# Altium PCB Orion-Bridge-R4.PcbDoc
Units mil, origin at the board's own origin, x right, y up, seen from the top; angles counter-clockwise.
Board outline 1889.76 x 1259.84 mil, 2 copper layers (Top Layer, Bottom Layer), stack 62.992 mil thick; 52 components, 35 nets, 164 pads, 41 vias.
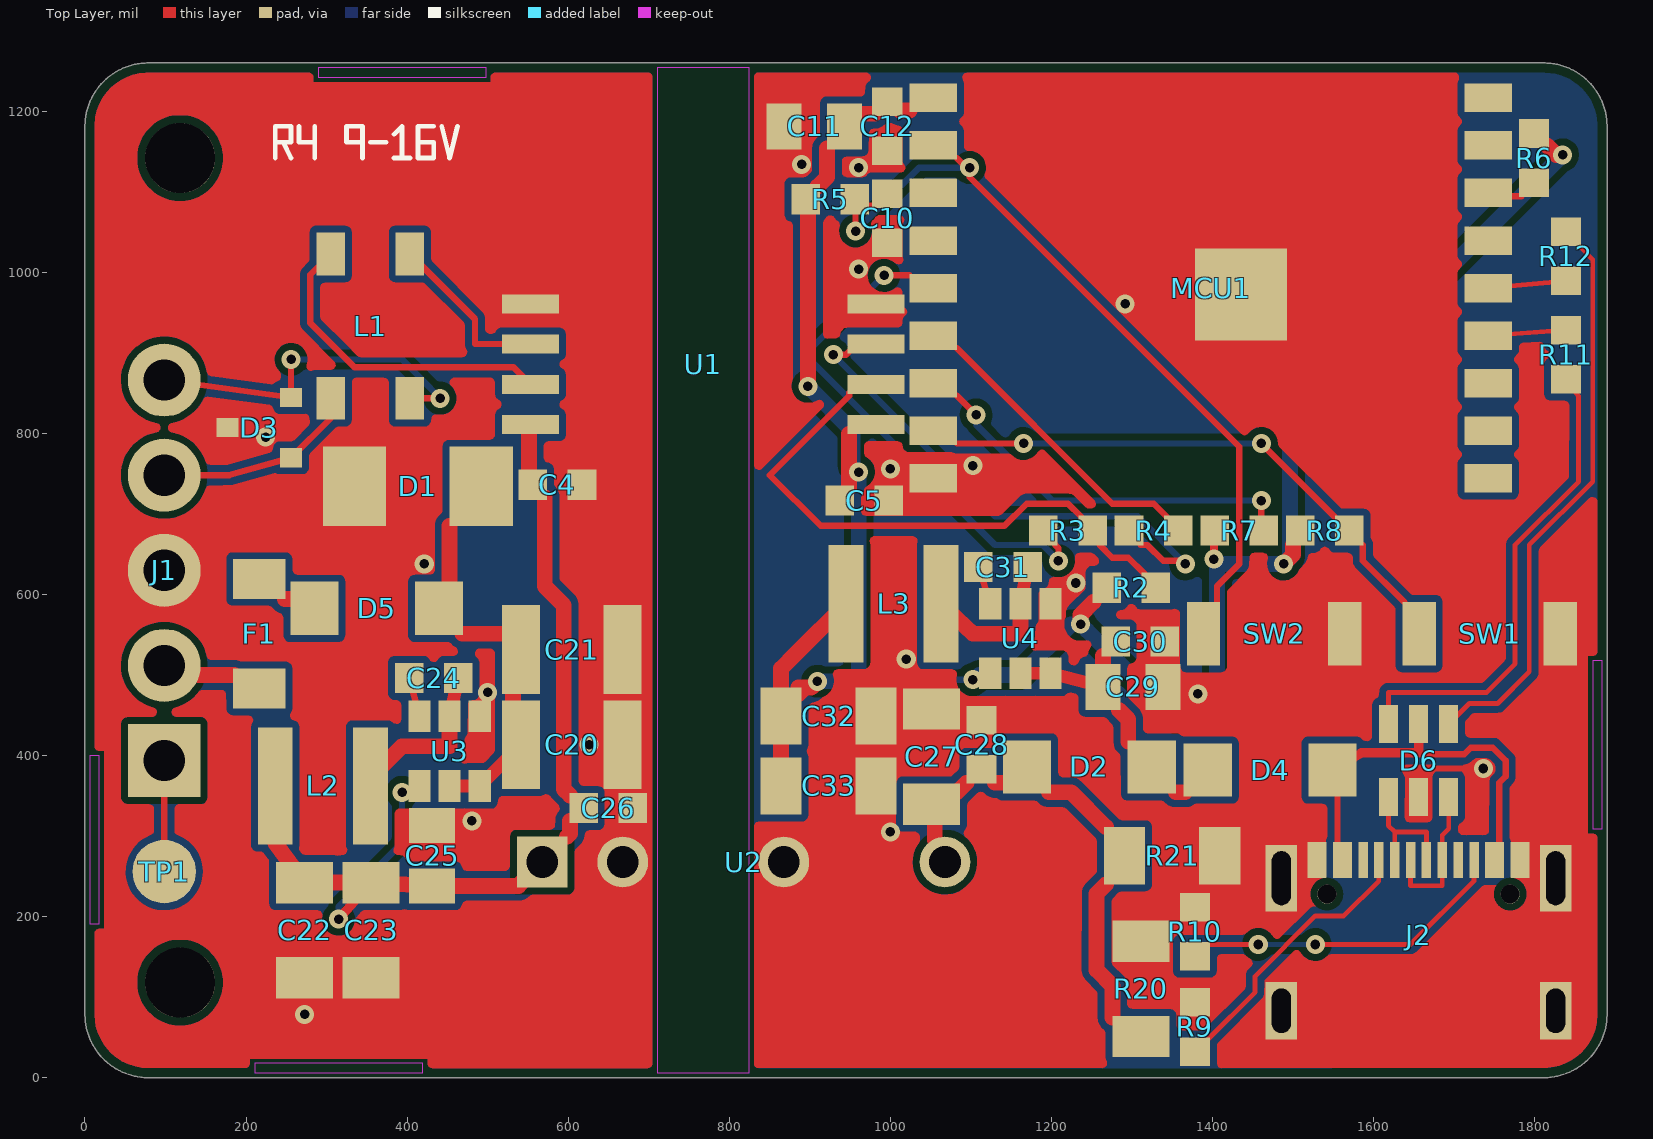
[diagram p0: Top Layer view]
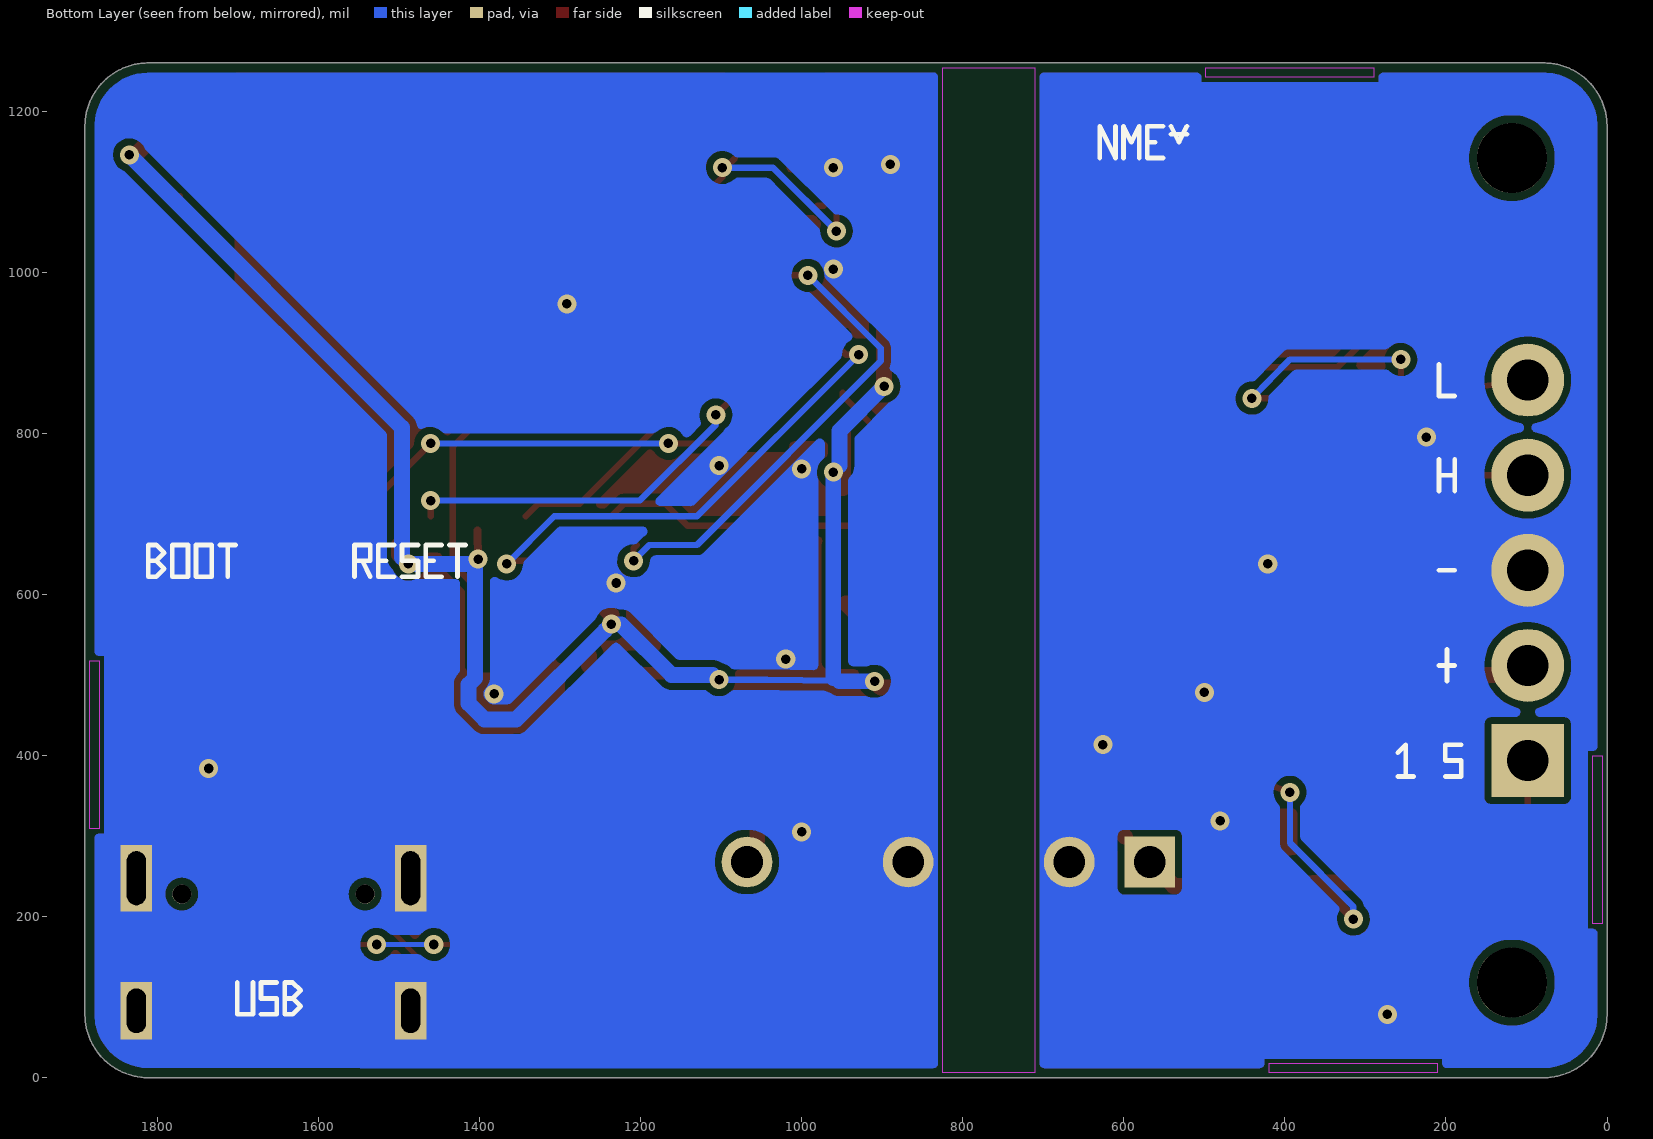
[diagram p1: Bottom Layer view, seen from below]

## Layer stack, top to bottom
Top Solder: solder mask 0.3937, Solder Resist, Dk 3.5
Top Layer: signal copper 1.378
Dielectric1: dielectric 60.2362, FR-4, Dk 4.3
Bottom Layer: signal copper 1.378
Bottom Solder: solder mask 0.3937, Solder Resist, Dk 3.5

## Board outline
1811.02,0 1812.96,0.02 1814.89,0.09 1816.82,0.21 1818.74,0.38 1820.66,0.59 1822.58,0.85 1824.49,1.16 1826.39,1.51 1828.28,1.91 1830.16,2.36 1832.02,2.85 1833.88,3.39 1835.72,3.97 1837.55,4.6 1839.36,5.28 1841.16,5.99 1842.93,6.76 1844.69,7.56 1846.43,8.41 1848.14,9.3 1849.83,10.23 1851.5,11.2 1853.15,12.22 1854.77,13.27 1856.36,14.36 1857.93,15.5 1859.47,16.67 1860.98,17.87 1862.45,19.12 1863.9,20.4 1865.32,21.71 1866.7,23.06 1868.05,24.45 1869.37,25.86 1870.65,27.31 1871.89,28.79 1873.1,30.3 1874.27,31.83 1875.4,33.4 1876.49,34.99 1877.55,36.61 1878.56,38.26 1879.53,39.93 1880.47,41.62 1881.36,43.34 1882.2,45.07 1883.01,46.83 1883.77,48.61 1884.49,50.4 1885.16,52.21 1885.79,54.04 1886.37,55.88 1886.91,57.74 1887.4,59.61 1887.85,61.49 1888.25,63.38 1888.6,65.28 1888.91,67.19 1889.17,69.1 1889.38,71.02 1889.55,72.95 1889.67,74.88 1889.74,76.81 1889.76,78.74 1889.76,1181.1 1889.74,1183.03 1889.67,1184.97 1889.55,1186.89 1889.38,1188.82 1889.17,1190.74 1888.91,1192.66 1888.6,1194.56 1888.25,1196.46 1887.85,1198.35 1887.4,1200.23 1886.91,1202.1 1886.37,1203.96 1885.79,1205.8 1885.16,1207.63 1884.49,1209.44 1883.77,1211.23 1883.01,1213.01 1882.2,1214.77 1881.36,1216.5 1880.47,1218.22 1879.53,1219.91 1878.56,1221.58 1877.55,1223.23 1876.49,1224.85 1875.4,1226.44 1874.27,1228.01 1873.1,1229.55 1871.89,1231.05 1870.65,1232.53 1869.37,1233.98 1868.05,1235.4 1866.7,1236.78 1865.32,1238.13 1863.9,1239.44 1862.45,1240.73 1860.98,1241.97 1859.47,1243.18 1857.93,1244.35 1856.36,1245.48 1854.77,1246.57 1853.15,1247.63 1851.5,1248.64 1849.83,1249.61 1848.14,1250.55 1846.43,1251.43 1844.69,1252.28 1842.93,1253.09 1841.16,1253.85 1839.36,1254.57 1837.55,1255.24 1835.72,1255.87 1833.88,1256.45 1832.02,1256.99 1830.16,1257.48 1828.28,1257.93 1826.39,1258.33 1824.49,1258.68 1822.58,1258.99 1820.66,1259.25 1818.74,1259.46 1816.82,1259.63 1814.89,1259.75 1812.96,1259.82 1811.02,1259.84 78.74,1259.84 76.81,1259.82 74.88,1259.75 72.95,1259.63 71.02,1259.46 69.1,1259.25 67.19,1258.99 65.28,1258.68 63.38,1258.33 61.49,1257.93 59.61,1257.48 57.74,1256.99 55.88,1256.45 54.04,1255.87 52.21,1255.24 50.4,1254.57 48.61,1253.85 46.83,1253.09 45.07,1252.28 43.34,1251.43 41.62,1250.55 39.93,1249.61 38.26,1248.64 36.61,1247.63 34.99,1246.57 33.4,1245.48 31.83,1244.35 30.3,1243.18 28.79,1241.97 27.31,1240.73 25.86,1239.44 24.45,1238.13 23.06,1236.78 21.71,1235.4 20.4,1233.98 19.12,1232.53 17.87,1231.05 16.67,1229.55 15.5,1228.01 14.36,1226.44 13.27,1224.85 12.22,1223.23 11.2,1221.58 10.23,1219.91 9.3,1218.22 8.41,1216.5 7.56,1214.77 6.76,1213.01 5.99,1211.23 5.28,1209.44 4.6,1207.63 3.97,1205.8 3.39,1203.96 2.85,1202.1 2.36,1200.23 1.91,1198.35 1.51,1196.46 1.16,1194.56 0.85,1192.66 0.59,1190.74 0.38,1188.82 0.21,1186.89 0.09,1184.97 0.02,1183.03 0,1181.1 0,78.74 0.02,76.81 0.09,74.88 0.21,72.95 0.38,71.02 0.59,69.1 0.85,67.19 1.16,65.28 1.51,63.38 1.91,61.49 2.36,59.61 2.85,57.74 3.39,55.88 3.97,54.04 4.6,52.21 5.28,50.4 5.99,48.61 6.76,46.83 7.56,45.07 8.41,43.34 9.3,41.62 10.23,39.93 11.2,38.26 12.22,36.61 13.27,34.99 14.36,33.4 15.5,31.83 16.67,30.3 17.87,28.79 19.12,27.31 20.4,25.86 21.71,24.45 23.06,23.06 24.45,21.71 25.86,20.4 27.31,19.12 28.79,17.87 30.3,16.67 31.83,15.5 33.4,14.36 34.99,13.27 36.61,12.22 38.26,11.2 39.93,10.23 41.62,9.3 43.34,8.41 45.07,7.56 46.83,6.76 48.61,5.99 50.4,5.28 52.21,4.6 54.04,3.97 55.88,3.39 57.74,2.85 59.61,2.36 61.49,1.91 63.38,1.51 65.28,1.16 67.19,0.85 69.1,0.59 71.02,0.38 72.95,0.21 74.88,0.09 76.81,0.02 78.74,0

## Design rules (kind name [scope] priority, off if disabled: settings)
BoardOutlineClearance BoardEdge_0_30mm [All] p1: gap=11.81 ignorepadtopadclearanceinfootprint=FALSE
Clearance Isolation_BUS_LOGIC [InNet('5V_BUS') Or InNet('BST_BUS') Or InNet('BUS_PROT') Or InNet('CANH') Or InNet('CANH_EXT') Or InNet('CANL') Or InNet('CANL_EXT') Or InNet('FUSED_IN') Or InNet('GND_BUS') Or InNet('NET_S') Or InNet('SHIELD') Or InNet('SW_BUS') vs InNet('3V3_LOGIC') Or InNet('5V_ISO') Or InNet('5V_SYS') Or InNet('BST_LOGIC') Or InNet('ESP_BOOT') Or InNet('ESP_EN') Or InNet('ESP_GPIO2') Or InNet('ESP_GPIO8') Or InNet('GND_LOGIC') Or InNet('GPIO6') Or InNet('GPIO7') Or InNet('RXD') Or InNet('SW_LOGIC') Or InNet('TXD') Or InNet('USB_CC1') Or InNet('USB_CC2') Or InNet('USB_DM') Or InNet('USB_DM_IN') Or InNet('USB_DM_MCU') Or InNet('USB_DP') Or InNet('USB_DP_IN') Or InNet('USB_DP_MCU') Or InNet('USB_VBUS')] p1: gap=125.98 ignorepadtopadclearanceinfootprint=FALSE
Clearance Mounting_NPTH [IsPad And (HoleSize > 0) And (PadIsPlated = 'False') And (Not InComponent('J2'))] p2: gap=9.84 ignorepadtopadclearanceinfootprint=FALSE
Clearance USB_Alignment_NPTH [IsPad And (HoleSize > 0) And (PadIsPlated = 'False') And InComponent('J2')] p3: gap=7.87 ignorepadtopadclearanceinfootprint=FALSE
Clearance [All] p4: gap=5.91 ignorepadtopadclearanceinfootprint=FALSE
ComponentClearance [All] p1: gap=9.84 collisioncheckmode=3 verticalgap=9.84 showdistances=FALSE
HoleSize [All] p1: absolutevalues=TRUE maxlimit=248.03 minlimit=11.81 maxpercent=80.000 minpercent=20.000
HoleToHoleClearance [All] p1: gap=9.84 allowstackedmicrovias=FALSE
MinimumAnnularRing PTH_AnnularRing [IsPad And (PadIsPlated = 'True')] p1: minimumring=7.09
MinimumAnnularRing Via_AnnularRing [IsVia] p2: minimumring=5.91
MinimumSolderMaskSliver [All] p1: minsoldermaskwidth=3.94
PasteMaskExpansion Paste_1to1 [All] p1: expansion=0
PolygonConnect [All] p1: connectstyle=Relief reliefconductorwidth=10 reliefentries=4 polygonreliefangle="90 Angle" airgapwidth=10
RoutingVias [All] p1: holewidth=11.81 width=23.62 viastyle="Through Hole" minholewidth=11.81 minwidth=23.62 maxholewidth=11.81 maxwidth=23.62
SilkToSilkClearance SilkToSilk [All] p1: silktosilkclearance=3.94
SilkToSolderMaskClearance SilkToMask_0_15mm [IsPad] p1: minsilkscreentomaskgap=5.91 clearancetoexposedcopper=FALSE
SolderMaskExpansion TentedVias [IsVia] p1: expansion=-11.81 istentingtop=TRUE
SolderMaskExpansion PadSolderMask [All] p2: expansion=1.97 istentingtop=FALSE
SupplyNets "Schematic Supply Nets_1" [InNet('GND_BUS')] p1: voltage=0.000
SupplyNets "Schematic Supply Nets" [InNet('GND_LOGIC')] p2: voltage=0.000
Width USB_FullSpeed [InNet('USB_CC1') Or InNet('USB_CC2') Or InNet('USB_DM') Or InNet('USB_DM_IN') Or InNet('USB_DM_MCU') Or InNet('USB_DP') Or InNet('USB_DP_IN') Or InNet('USB_DP_MCU')] p1: maxlimit=19.68 minlimit=5.91 preferedwidth=5.91
Width [All] p2: maxlimit=78.74 minlimit=7.87 preferedwidth=11.81
23 further rules are at their usual default settings.

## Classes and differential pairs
component class Orion-Bridge-R4-Power: C20 C21 C22 C23 C24 C25 C26 C27 C28 C29 C30 C31 C32 C33 D1 D2 D4 D5 F1 J1 L2 L3 R20 R21 TP1 U2 U3 U4
component class Orion-Bridge-R4-Logic: C4 C5 C10 C11 C12 D3 D6 J2 L1 MCU1 R2 R3 R4 R5 R6 R7 R8 R9 R10 R11 R12 SW1 SW2 U1

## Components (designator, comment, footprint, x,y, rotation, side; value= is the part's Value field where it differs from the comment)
C4 "100nF 50V X7R" C0603#1 586.61,736.22 r0 top
C5 "100nF 50V X7R" C0603#2 967.52,716.54 r0 top
C10 "1uF 50V X5R" C0603#2 996.06,1066.93 r270 top
C11 "10uF 25V X5R" C0805 905.51,1181.1 r180 top
C12 "100nF 50V X7R" C0603#2 996.06,1181.1 r270 top
C20 "10uF 50V X7R" C1210#1 604.33,413.39 r0 top
C21 "10uF 50V X7R" C1210#2 604.33,531.5 r0 top
C22 "22uF 25V X5R" C1206 272.64,183.07 r270 top
C23 "22uF 25V X5R" C1206 355.31,183.07 r270 top
C24 "100nF 50V X7R" C0603#2 433.07,496.06 r0 top
C25 "10uF 25V X5R" C0805 431.1,275.59 r90 top
C26 "100nF 50V X7R" C0603#3 649.61,334.65 r0 top
C27 "22uF 25V X5R" C1206 1051.18,398.62 r90 top
C28 "100nF 50V X7R" C0603#4 1113.19,413.39 r90 top
C29 "10uF 25V X5R" C0805 1301.18,485.24 r0 top
C30 "100nF 50V X7R" C0603#2 1310.04,541.34 r0 top
C31 "100nF 50V X7R" C0603#5 1139.76,633.86 r0 top
C32 "22uF 25V X5R" C1206 923.23,448.82 r0 top
C33 "22uF 25V X5R" C1206 923.23,362.2 r0 top
D1 "SMBJ18A 600W" SMB 413.39,734.25 r180 top
D2 "SS14 1A 40V" SMA#1 1247.05,385.83 r180 top
D3 "PESD2CAN24T-Q" SOT23_NEXPERIA_REFLOW 216.54,807.09 r90 top
D4 "SS14 1A 40V" SMA#1 1471.46,381.89 r0 top
D5 "SS26 2A 60V" SMA#2 362.2,582.68 r180 top
D6 "USBLC6-2SC6" SOT23_6_ST_USBLC6 1655.71,393.7 r0 top
F1 "T0.8A 63VDC" BOURNS_SF1206S 216.54,551.18 r90 top
J1 "NMEA Micro-C pigtail" PIGTAIL_5_P3_D1P3 98.43,629.92 r180 top
J2 "TYPE-C-31-M-12" USB_C_HRO_TYPE_C_31_M_12_2020 1655.71,125.59 r0 top
L1 "ACT45B-510-2P-TL003" ACT45B 354.33,933.07 r90 top
L2 "4.7uH" SUNLORD_SWPA4030 295.28,362.2 r180 top
L3 "4.7uH" SUNLORD_SWPA4030 1003.94,588.58 r180 top
MCU1 "ESP32-C3-WROOM-02-N4" ESP32_C3_WROOM_02 1397.64,1102.36 r0 top
R2 "10k 1% 0.1W" R0603 1299.21,608.27 r0 top
R3 "33R" R0603 1220.47,679.13 r0 top
R4 "33R" R0603 1326.77,679.13 r0 top
R5 "10k 1% 0.1W" R0603 925.2,1090.55 r0 top
R6 "10k 1% 0.1W" R0603 1799.21,1141.73 r270 top
R7 "10k 1% 0.1W" R0603 1433.07,679.13 r0 top
R8 "10k 1% 0.1W" R0603 1539.37,679.13 r0 top
R9 "5.1k 1% 0.1W" R0603 1377.95,62.99 r90 top
R10 "5.1k 1% 0.1W" R0603 1377.95,181.1 r90 top
R11 "22R 1% 0.1W" R0603 1838.58,897.64 r90 top
R12 "22R 1% 0.1W" R0603 1838.58,1019.68 r270 top
R20 "150R 1% 0.5W" R1206 1311.02,110.24 r90 top
R21 "150R 1% 0.5W" R1206 1349.8,275.59 r0 top
SW1 "TS-1088-AR02016" SW_XUNPU_TS1088_AR 1744.09,551.18 r0 top
SW2 "TS-1088-AR02016" SW_XUNPU_TS1088_AR 1476.38,551.18 r0 top
TP1 "Shield / chassis pad" TESTPOINT_2MM 98.43,255.91 r0 top
U1 "ISO1042DWV" SOIC8_DWV 767.72,885.83 r180 top
U2 "B0505S-3WR2" EVISUN_B0505S_3WR2 867.52,165.35 r0 top
U3 "AP63205WU-7" TSOT26_DIODES 452.76,405.51 r0 top
U4 "AP63203WU-7" TSOT26_DIODES 1161.42,545.28 r0 top

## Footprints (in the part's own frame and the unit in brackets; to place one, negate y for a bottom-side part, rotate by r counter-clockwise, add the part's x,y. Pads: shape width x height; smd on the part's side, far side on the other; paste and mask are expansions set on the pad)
ACT45B [mm] "TDK ACT45B recommended lands; windings 1-4 and 2-3"
  rect 1.35x0.9 smd: 1(-2.275,1.25) 2(-2.275,-1.25) 3(2.275,-1.25) 4(2.275,1.25)
  body extent -2.53,-1.6 2.52,1.6, height 2.8
BOURNS_SF1206S [mm] "Bourns SF-1206S recommended land pattern: total X span 4.7, inner gap 2.2, pad Y 1.65; maximum body envelope. No polarity."
  rect 1.25x1.65 smd: 1(-1.725,0)
  rect 1.25x1.65 smd mask+0.02: 2(1.725,0)
  body extent -1.6,-0.83 1.6,0.83, height 0.71
C0603#1 [mm] "IPC-style 0603 solder lands; selected MPN dimensions reviewed separately."
  rect 0.9x0.95 smd mask+0.015: 1(-0.775,0)
  rect 0.9x0.95 smd: 2(0.775,0)
  body extent -0.8,-0.41 0.8,0.41, height 0.81
C0603#2 [mm] "IPC-style 0603 solder lands; selected MPN dimensions reviewed separately."
  rect 0.9x0.95 smd: 1(-0.775,0) 2(0.775,0)
  body extent -0.8,-0.41 0.8,0.41, height 0.81
C0603#3 [mm] "IPC-style 0603 solder lands; selected MPN dimensions reviewed separately."
  rect 0.9x0.95 smd mask+0.01: 1(-0.775,0) 2(0.775,0)
  body extent -0.8,-0.41 0.8,0.41, height 0.81
C0603#4 [mm] "IPC-style 0603 solder lands; selected MPN dimensions reviewed separately."
  rect 0.9x0.95 smd: 1(-0.775,0)
  rect 0.9x0.95 smd mask+0.025: 2(0.775,0)
  body extent -0.8,-0.41 0.8,0.41, height 0.81
C0603#5 [mm] "IPC-style 0603 solder lands; selected MPN dimensions reviewed separately."
  rect 0.9x0.95 smd mask+0.015: 1(-0.775,0) 2(0.775,0)
  body extent -0.8,-0.41 0.8,0.41, height 0.81
C0805 [mm] "IPC-style 0805 solder lands; selected MPN dimensions reviewed separately."
  rect 1.1x1.45 smd: 1(-0.95,0) 2(0.95,0)
  body extent -1,-0.63 1,0.63, height 0.81
C1206 [mm] "IPC-style 1206 solder lands; selected MPN dimensions reviewed separately."
  rect 1.3x1.8 smd: 1(-1.5,0) 2(1.5,0)
  body extent -1.6,-0.81 1.6,0.81, height 1.52
C1210#1 [mm] "Samsung CL32B106KBJNNNE body3.2x2.5mm, nominal1210 land pattern selected."
  rect 1.2x2.8 smd: 1(-1.6,0)
  rect 1.2x2.8 smd mask+0.01: 2(1.6,0)
  body extent -1.6,-1.26 1.6,1.26, height 2.72
C1210#2 [mm] "Samsung CL32B106KBJNNNE body3.2x2.5mm, nominal1210 land pattern selected."
  rect 1.2x2.8 smd: 1(-1.6,0) 2(1.6,0)
  body extent -1.6,-1.26 1.6,1.26, height 2.72
ESP32_C3_WROOM_02 [mm] "Espressif WROOM-02 v1.7 Fig11-1. EP19 ground copper with NO paste; optional EP left unsoldered per manufacturer."
  rect 1.5x0.9 smd: 1(-8.75,2.9) 2(-8.75,1.4) 3(-8.75,-0.1) 4(-8.75,-1.6) 9(-8.75,-9.1) 10(8.75,-9.1) 11(8.75,-7.6) 12(8.75,-6.1) 13(8.75,-4.6) 14(8.75,-3.1) 15(8.75,-1.6) 16(8.75,-0.1) 17(8.75,1.4) 18(8.75,2.9)
  rect 1.5x0.9 smd mask+0.02: 5(-8.75,-3.1) 6(-8.75,-4.6) 7(-8.75,-6.1) 8(-8.75,-7.6)
  rect 2.9x2.9 smd paste-10: 19(0.96,-3.3)
  body extent -9,-10 9,10, height 3.35
EVISUN_B0505S_3WR2 [mm] "EVISUN p4: nominal19.65x7x10.16mm, unspecified body tolerance+/-0.25mm, lead1 x=2.21 from body left, pitch1-2=2.54/2-4=5.08/4-6=5.08mm. Pin row .90mm from long body edge. Bottom view mirrored vertically to PCB TOP: row Y=+2.60mm. Finished holes1.00mm, annulus.30mm. Primary/secondary pad copper gap3.48mm."
  rect 1.6x1.6 hole 1 paste-2539.97: 1(-7.615,2.6)
  round 1.6 hole 1 paste-2539.97: 2(-5.075,2.6) 4(0.005,2.6) 6(5.085,2.6)
  body extent -9.82,-3.5 9.82,3.5, height 10.33
PIGTAIL_5_P3_D1P3 [mm] "Designed carrier wire-solder interface, 3.0 pitch, 1.3 finished-hole target, 0.5 radial annulus. Pin numbering is logical NMEA: 1 shield, 2 NET-S, 3 NET-C, 4 CAN-H, 5 CAN-L. Cable and strain relief still require a physical selection."
  rect 2.3x2.3 hole 1.3 paste-2539.97: 1(0,6)
  round 2.3 hole 1.3 paste-2539.97: 2(0,3) 3(0,0) 4(0,-3) 5(0,-6)
  body extent -1.15,-7.15 1.15,7.15, height 0.06
R0603 [mm] "IPC-style 0603 solder lands; selected MPN dimensions reviewed separately."
  rect 0.9x0.95 smd: 1(-0.775,0) 2(0.775,0)
  body extent -0.8,-0.41 0.8,0.41, height 0.81
R1206 [mm] "IPC-style 1206 solder lands; selected MPN dimensions reviewed separately."
  rect 1.3x1.8 smd: 1(-1.5,0) 2(1.5,0)
  body extent -1.6,-0.81 1.6,0.81, height 1.52
SMA#1 [mm] "MDD SS12-SS1200 Rev2025A3 p3 / SS22-SS2200 Rev2024A4 p3 suggested SMA pattern: pad1.52x1.68, centrepitch3.93, innergap2.41, totalX5.45mm. Maxbody4.5x2.8x2.45; pin1Kleft,2Aright. Visually checked selected C2480/C14238 PDFs."
  rect 1.52x1.68 smd: 1(-1.965,0) 2(1.965,0)
  body extent -2.54,-1.4 2.54,1.4, height 2.46
SMA#2 [mm] "MDD SS12-SS1200 Rev2025A3 p3 / SS22-SS2200 Rev2024A4 p3 suggested SMA pattern: pad1.52x1.68, centrepitch3.93, innergap2.41, totalX5.45mm. Maxbody4.5x2.8x2.45; pin1Kleft,2Aright. Visually checked selected C2480/C14238 PDFs."
  rect 1.52x1.68 smd: 1(-1.965,0)
  rect 1.52x1.68 smd mask+0.02: 2(1.965,0)
  body extent -2.54,-1.4 2.54,1.4, height 2.46
SMB [mm] "BORN SMBJ Series Rev2022-Jan-1-A p7 manufacturer pattern: pad2.0x2.5mm, innergap2.0mm, centres+/-2.0mm; maxbody4.7x3.9x2.5; pin1Kleft,2Aright. Visually checked selected C152104 PDF."
  rect 2x2.5 smd: 1(-2,0) 2(2,0)
  body extent -2.58,-1.95 2.57,1.95, height 2.51
SOIC8_DWV [mm] "TI DWV0008A manufacturer land pattern; pin 1 upper left"
  rect 1.8x0.6 smd mask+0.02: 1(-5.45,1.905) 2(-5.45,0.635) 3(-5.45,-0.635) 4(-5.45,-1.905)
  rect 1.8x0.6 smd: 5(5.45,-1.905) 6(5.45,-0.635) 7(5.45,0.635) 8(5.45,1.905)
  body extent -5.7,-2.93 5.7,2.93, height 2.82
SOT23_6_ST_USBLC6 [mm] "ST USBLC6-2 datasheet Fig22 p12; visually checked manufacturer recommended land pattern."
  rect 0.6x1.2 smd: 1(-0.95,-1.15) 2(0,-1.15) 3(0.95,-1.15) 4(0.95,1.15) 5(0,1.15) 6(-0.95,1.15)
  body extent -1.53,-1.4 1.52,1.4, height 1.47
SOT23_NEXPERIA_REFLOW [mm] "Nexperia SOT23 reflow footprint Fig10: 0.6 x 0.7 copper lands, 1.9 pin pitch and 2.0 row centres. Drawing is rotated 180 degrees to match existing top-view pin1 lower left, pin2 lower right, pin3 upper centre. Paste suggested0.5 x0.6, mask opening1.0 x1.0; set fabrication-specific expansions accordingly."
  rect 0.6x0.7 smd: 1(-0.95,-1) 2(0.95,-1) 3(0,1)
  body extent -1.5,-1.25 1.5,1.25, height 1.11
SUNLORD_SWPA4030 [mm] "Sunlord SWPA datasheet2025-05-08 p2 recommended SWPA4030S pattern: gap1.9, padwidth1.1, padheight3.7."
  rect 1.1x3.7 smd: 1(-1.5,0) 2(1.5,0)
  body extent -2,-2 2,2, height 3.02
SW_XUNPU_TS1088_AR [mm] "XUNPU TS-1088-ARXXXXXX manufacturer drawing: outer width5.50, inner gap3.40, padheight2.00; two terminals, no locating posts."
  rect 1.05x2 smd: 1(-2.225,0) 2(2.225,0)
  body extent -2.68,-1.5 2.67,1.5, height 2
TESTPOINT_2MM [mm] "2 mm exposed top-copper test pad; no paste"
  round 2 smd paste-10: 1(0,0)
  body extent -1,-1 1,1, height 0.06
TSOT26_DIODES [mm] "Diodes DS41326 Rev3-2 p17 suggested TSOT26 copper: X=.70,Y=1.00,Y1=3.20 total span,C=.95. Top view: pin1 lower-left; pin4 upper-right."
  rect 0.7x1 smd: 1(-0.95,-1.1) 2(0,-1.1) 3(0.95,-1.1) 4(0.95,1.1) 5(0,1.1) 6(-0.95,1.1)
  body extent -1.5,-1.35 1.5,1.35, height 1.01
USB_C_HRO_TYPE_C_31_M_12_2020 [mm] "HRO drawing dated2020-12-08 downloaded via JLC C165948. NOT older2018 KiCad footprint: updated front slots1.4, padwidth centres3.20/2.40 and padheight1.14. Body envelope3D is nominal. Shield copper enlarged by0.05mm peredge from manufacturer recommendation to provide0.20mm annular ring; drills unchanged."
  rect 0.6x1.14 smd: A1_B12(-3.2,3.67) A4_B9(-2.4,3.67) B1_A12(3.2,3.67) B4_A9(2.4,3.67)
  rect 0.3x1.14 smd: A5(-1.25,3.67) A6(-0.25,3.67) A7(0.25,3.67) A8(1.25,3.67) B5(1.75,3.67) B6(0.75,3.67) B7(-0.75,3.67) B8(-1.75,3.67)
  rect 1x2.1 hole 0.6 slot 1.7 at 90 deg paste-2539.97: S1(-4.325,3.1) S2(4.325,3.1)
  rect 1x1.8 hole 0.6 slot 1.4 at 90 deg paste-2539.97: S3(-4.325,-1.08) S4(4.325,-1.08)
  round 0.6 hole 0.6 unplated paste-2539.97 mask+0.05: ""(-2.89,2.6) ""(2.89,2.6)
  body extent -4.47,-3.68 4.47,4.14, height 3.26

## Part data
C4: library part R4_C4_100nF, "100nF 16V X7R - generic specification; manufacturer/MPN not selected", Manufacturer=YAGEO, Manufacturer Part Number=CC0603KRX7R9BB104, Supplier Part Number 1=C14663
C5: library part R4_C5_100nF, "100nF 16V X7R - generic specification; manufacturer/MPN not selected", Manufacturer=YAGEO, Manufacturer Part Number=CC0603KRX7R9BB104, Supplier Part Number 1=C14663
C10: library part R4_C10_1uF, Manufacturer="Samsung Electro-Mechanics", Manufacturer Part Number=CL10A105KB8NNNC, Supplier Part Number 1=C15849
C11: library part R4_C11_10uF, Manufacturer="Samsung Electro-Mechanics", Manufacturer Part Number=CL21A106KAYNNNE, Supplier Part Number 1=C15850
C12: library part R4_C12_100nF, Manufacturer=YAGEO, Manufacturer Part Number=CC0603KRX7R9BB104, Supplier Part Number 1=C14663
C20: library part R4_C20_10uF, Manufacturer="Samsung Electro-Mechanics", Manufacturer Part Number=CL32B106KBJNNNE, Supplier Part Number 1=C138687
C21: library part R4_C21_10uF, Manufacturer="Samsung Electro-Mechanics", Manufacturer Part Number=CL32B106KBJNNNE, Supplier Part Number 1=C138687
C22: library part R4_C22_22uF, Manufacturer="Samsung Electro-Mechanics", Manufacturer Part Number=CL31A226KAHNNNE, Supplier Part Number 1=C12891
C23: library part R4_C23_22uF, Manufacturer="Samsung Electro-Mechanics", Manufacturer Part Number=CL31A226KAHNNNE, Supplier Part Number 1=C12891
C24: library part R4_C24_100nF, Manufacturer=YAGEO, Manufacturer Part Number=CC0603KRX7R9BB104, Supplier Part Number 1=C14663
C25: library part R4_C25_10uF, Manufacturer="Samsung Electro-Mechanics", Manufacturer Part Number=CL21A106KAYNNNE, Supplier Part Number 1=C15850
C26: library part R4_C26_100nF, Manufacturer=YAGEO, Manufacturer Part Number=CC0603KRX7R9BB104, Supplier Part Number 1=C14663
C27: library part R4_C27_22uF, Manufacturer="Samsung Electro-Mechanics", Manufacturer Part Number=CL31A226KAHNNNE, Supplier Part Number 1=C12891
C28: library part R4_C28_100nF, Manufacturer=YAGEO, Manufacturer Part Number=CC0603KRX7R9BB104, Supplier Part Number 1=C14663
C29: library part R4_C29_10uF, Manufacturer="Samsung Electro-Mechanics", Manufacturer Part Number=CL21A106KAYNNNE, Supplier Part Number 1=C15850
C30: library part R4_C30_100nF, Manufacturer=YAGEO, Manufacturer Part Number=CC0603KRX7R9BB104, Supplier Part Number 1=C14663
C31: library part R4_C31_100nF, Manufacturer=YAGEO, Manufacturer Part Number=CC0603KRX7R9BB104, Supplier Part Number 1=C14663
C32: library part R4_C32_22uF, Manufacturer="Samsung Electro-Mechanics", Manufacturer Part Number=CL31A226KAHNNNE, Supplier Part Number 1=C12891
C33: library part R4_C33_22uF, Manufacturer="Samsung Electro-Mechanics", Manufacturer Part Number=CL31A226KAHNNNE, Supplier Part Number 1=C12891
D1: library part R4_D1_SMBJ18A, Manufacturer=BORN, Manufacturer Part Number=SMBJ18A, Supplier Part Number 1=C152104
D2: library part R4_D2_SS14, Manufacturer="MDD(Microdiode Semiconductor)", Manufacturer Part Number=SS14, Supplier Part Number 1=C2480
D3: library part R4_D3_PESD2CAN24T_Q, Manufacturer=Nexperia, Manufacturer Part Number=PESD2CAN24T-QR, Supplier Part Number 1=C28933048
D4: library part R4_D4_SS14, Manufacturer="MDD(Microdiode Semiconductor)", Manufacturer Part Number=SS14, Supplier Part Number 1=C2480
D5: library part R4_D5_SS26, Manufacturer="MDD(Microdiode Semiconductor)", Manufacturer Part Number=SS26, Supplier Part Number 1=C14238
D6: library part R4_D6_USBLC6_2SC6, Manufacturer=STMicroelectronics, Supplier Part Number 1=C7519
F1: library part R4_F1_T0.8A, "0.8 A slow-blow SMD ceramic fuse, 63 VDC, 50 A interrupt rating", Manufacturer=BOURNS, Manufacturer Part Number=SF-1206S080-2, Supplier Part Number 1=C3032873
J1: library part R4_J1_NMEA, "Five direct wire-solder pads for a separately selected Micro-C cable; this is a PCB interface, not an invented connector MPN or face view"
J2: library part R4_J2_TYPE_C_31_M_12, Manufacturer="Korean Hroparts Elec", Supplier Part Number 1=C165948
L1: library part R4_L1_ACT45B_510_2P_TL003, Manufacturer=TDK, Supplier Part Number 1=C76584
L2: library part R4_L2_4.7uH, Manufacturer=Sunlord, Manufacturer Part Number=SWPA4030S4R7MT, Supplier Part Number 1=C57269
L3: library part R4_L3_4.7uH, Manufacturer=Sunlord, Manufacturer Part Number=SWPA4030S4R7MT, Supplier Part Number 1=C57269
MCU1: library part R4_MCU1_ESP32_C3_WROOM_02_N4, Manufacturer="Espressif Systems", Supplier Part Number 1=C2934560
R2: library part R4_R2_10k, "10k - generic specification; manufacturer/MPN not selected", Manufacturer="UNI-ROYAL(Uniroyal Elec)", Manufacturer Part Number=0603WAF1002T5E, Supplier Part Number 1=C25804
R3: library part R4_R3_33R, "33R - generic specification; manufacturer/MPN not selected", Manufacturer="UNI-ROYAL(Uniroyal Elec)", Manufacturer Part Number=0603WAF330JT5E, Supplier Part Number 1=C23140
R4: library part R4_R4_33R, "33R - generic specification; manufacturer/MPN not selected", Manufacturer="UNI-ROYAL(Uniroyal Elec)", Manufacturer Part Number=0603WAF330JT5E, Supplier Part Number 1=C23140
R5: library part R4_R5_10k, Manufacturer="UNI-ROYAL(Uniroyal Elec)", Manufacturer Part Number=0603WAF1002T5E, Supplier Part Number 1=C25804
R6: library part R4_R6_10k, Manufacturer="UNI-ROYAL(Uniroyal Elec)", Manufacturer Part Number=0603WAF1002T5E, Supplier Part Number 1=C25804
R7: library part R4_R7_10k, Manufacturer="UNI-ROYAL(Uniroyal Elec)", Manufacturer Part Number=0603WAF1002T5E, Supplier Part Number 1=C25804
R8: library part R4_R8_10k, Manufacturer="UNI-ROYAL(Uniroyal Elec)", Manufacturer Part Number=0603WAF1002T5E, Supplier Part Number 1=C25804
R9: library part R4_R9_5.1k, Manufacturer="UNI-ROYAL(Uniroyal Elec)", Manufacturer Part Number=0603WAF5101T5E, Supplier Part Number 1=C23186
R10: library part R4_R10_5.1k, Manufacturer="UNI-ROYAL(Uniroyal Elec)", Manufacturer Part Number=0603WAF5101T5E, Supplier Part Number 1=C23186
R11: library part R4_R11_22R, Manufacturer="UNI-ROYAL(Uniroyal Elec)", Manufacturer Part Number=0603WAF220JT5E, Supplier Part Number 1=C23345
R12: library part R4_R12_22R, Manufacturer="UNI-ROYAL(Uniroyal Elec)", Manufacturer Part Number=0603WAF220JT5E, Supplier Part Number 1=C23345
R20: library part R4_R20_150R, Manufacturer="SEI(Stackpole Elec)", Manufacturer Part Number=RNCP1206FTD150R, Supplier Part Number 1=C4258541
R21: library part R4_R21_150R, Manufacturer="SEI(Stackpole Elec)", Manufacturer Part Number=RNCP1206FTD150R, Supplier Part Number 1=C4258541
SW1: library part R4_SW1_TS_1088_AR02016, Manufacturer=XUNPU, Supplier Part Number 1=C720477
SW2: library part R4_SW2_TS_1088_AR02016, Manufacturer=XUNPU, Supplier Part Number 1=C720477
TP1: library part R4_TP1_Shield, "Shield / chassis pad - generic specification; manufacturer/MPN not selected"
U1: library part R4_U1_ISO1042DWV, Manufacturer="Texas Instruments", Manufacturer Part Number=ISO1042DWVR, Supplier Part Number 1=C2671714
U2: library part R4_U2_B0505S_3WR2, Manufacturer=EVISUN, Supplier Part Number 1=C7500927
U3: library part R4_U3_AP63205WU_7, Manufacturer="Diodes Incorporated", Supplier Part Number 1=C2071056
U4: library part R4_U4_AP63203WU_7, Manufacturer="Diodes Incorporated", Supplier Part Number 1=C780769

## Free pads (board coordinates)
  round 86.61 hole 86.61 unplated paste-99999 mask+1.97: ""(118.11,118.11) ""(118.11,1141.73)

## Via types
v1: diameter 23.62, hole 11.81, Top Layer to Bottom Layer, tented both sides, 41 vias

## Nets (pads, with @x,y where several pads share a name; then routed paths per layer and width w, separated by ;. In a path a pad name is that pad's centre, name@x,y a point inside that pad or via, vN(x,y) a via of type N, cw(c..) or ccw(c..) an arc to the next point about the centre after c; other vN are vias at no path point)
3V3_LOGIC: C5.1 C11.1 C12.1 C32.1 C33.1 L3.2 MCU1.1 R2.1 R5.1 R6.1 R7.1 R8.1 U1.1 U4.1 | length 2738.3
  Top Layer w7.87: v1(1102.36,494.09) U4.1
  Top Layer w9.84: C32.1 v1(909.45,492.13) ; v1(1401.57,643.7) R7.1
  Top Layer w19.68: C33.1 C32.1 864.17,507.87 881.89,525.59 L3.2 ; 885.83,484.25 901.57,484.25 v1(909.45,492.13) ; v1(897.64,858.27) R5.1@897.64,1074.8 ; R5.1@909.45,1106.3 921.26,1118.11 921.26,1153.54 ; C5.1@948.82,732.28 U1.1@948.82,799.21 ; v1@956.69,751.97 v1(960.63,751.97) ; C11.1@964.57,1196.85 C12.1@980.32,1196.85 ; C12.1@1011.81,1200.79 1023.62,1200.79 ; v1(1236.22,562.99) 1236.22,574.8 R2.1@1251.97,590.55 ; v1(1488.19,637.8) 1500,649.61 R8.1@1500,661.42 ; R6.1@1814.96,1157.48 1826.77,1145.67 v1(1834.65,1145.67)
  Bottom Layer w7.87: v1(909.45,492.13) 1043.31,494.09 v1(1102.36,494.09)
  Bottom Layer w19.68: v1(897.64,858.27) 952.76,803.15 v1@952.76,759.84 ; v1(909.45,492.13) 952.76,492.13 ; 960.63,496.06 v1(960.63,751.97) ; v1@1110.24,500 1161.42,500 1224.41,562.99 v1(1236.22,562.99) ; v1@1244.09,555.12 1354.33,444.88 1393.7,444.88 1413.39,464.57 1413.39,488.19 1405.51,496.06 v1@1405.51,633.86 ; 1413.39,637.8 v1(1488.19,637.8) ; v1@1496.06,645.67 1496.06,807.09 v1(1834.65,1145.67)
5V_BUS: C4.1 C22.1 C23.1 C25.1 C26.1 L2.2 U1.8 U2.1 U3.1 | length 1165
  Top Layer w7.87: v1(393.7,354.33) U3.1
  Top Layer w11.81: v1(314.96,196.85) C23.1
  Top Layer w19.68: L2.2 236.22,291.34 C22.1 C23.1 C25.1 538.19,238.19 U2.1 ; C4.1@551.18,751.97 U1.8@551.18,799.21 ; C4.1@570.87,720.47 570.87,610.24 594.49,586.61 594.49,358.27 C26.1@602.36,350.39 ; 598.43,299.21 602.36,303.15 C26.1@602.36,318.9
  Bottom Layer w7.87: v1(314.96,196.85) 314.96,212.6 393.7,291.34 v1(393.7,354.33)
5V_ISO: C27.1 C28.1 D2.2 R20.1 R21.1 U2.6 | length 315.4
  Top Layer w19.68: U2.6@1055.12,295.28 C27.1@1055.12,314.96 ; C27.1@1082.68,354.33 C28.1@1094.49,366.14 ; C28.1@1129.92,366.14 D2.2@1141.73,366.14 ; D2.2@1196.85,354.33 1224.41,354.33 R21.1@1267.72,311.02 ; 1267.72,240.16 1255.91,228.35 1255.91,133.86 1275.59,114.17 R20.1@1275.59,74.8
5V_SYS: C29.1 C30.1 D2.1 D4.1 U4.2 U4.3 | length 172.4
  Top Layer w15.75: U4.2 U4.3 C29.1
  Top Layer w19.68: C29.1@1263.78,511.81 C30.1@1263.78,523.62 ; C29.1@1283.46,456.69 1295.28,444.88 D2.1@1295.28,417.32 ; 1354.33,354.33 D4.1@1366.14,354.33
BST_BUS: C24.1 U3.6 | length 48.9
  Top Layer w7.87: C24.1 U3.6
BST_LOGIC: C31.1 U4.6 | length 47.6
  Top Layer w7.87: C31.1 U4.6
BUS_PROT: C20.1 C21.1 D1.1 D5.1 U3.2 U3.3 | length 239.7
  Top Layer w15.75: U3.2 U3.3 C20.1
  Top Layer w19.68: D5.1@452.76,614.17 D1.1@452.76,685.04 ; D5.1@468.5,551.18 C21.1@519.68,551.18 ; C20.1@531.5,468.5 C21.1@531.5,476.38
CANH: L1.4 U1.7 | length 401.4
  Top Layer w7.87: L1.4 279.53,997.05 279.53,937.01 334.65,881.89 532.09,881.89 U1.7
CANH_EXT: D3.1 J1.4 L1.1 | length 254.7
  Top Layer w7.87: J1.4 179.13,748.03 D3.1 305.12,818.9 L1.1
CANL: L1.3 U1.6 | length 214.1
  Top Layer w7.87: L1.3 484.25,941.93 484.25,910.83 U1.6
CANL_EXT: D3.2 J1.5 L1.2 | length 448.9
  Top Layer w7.87: J1.5 D3.2 v1(255.91,891.73) ; L1.2 v1(440.94,843.5)
  Bottom Layer w7.87: v1(255.91,891.73) 393.7,891.73 v1(440.94,843.5)
ESP_BOOT: MCU1.8 R8.2 SW1.1 | length 603.6
  Top Layer w7.87: 1082.68,787.4 v1(1165.35,787.4) ; v1(1460.63,787.4) R8.2@1555.12,692.91 ; R8.2@1586.61,661.42 1586.61,641.73 1637.8,590.55
  Bottom Layer w7.87: v1(1165.35,787.4) v1(1460.63,787.4)
ESP_EN: C10.1 MCU1.2 R5.2 SW2.1 | length 904.1
  Top Layer w7.87: v1(956.69,1051.18) R5.2@956.69,1074.8 ; R5.2@972.44,1082.68 C10.1@980.32,1082.68 ; 1082.68,1141.73 1094.49,1129.92 v1(1098.43,1129.92) ; 1098.43,1118.11 1433.07,783.46 1433.07,637.8 1405.51,610.24 1405.51,590.55
  Bottom Layer w7.87: v1(956.69,1051.18) 1035.43,1129.92 v1(1098.43,1129.92)
ESP_GPIO2: MCU1.16 R6.2 | length 11.8
  Top Layer w7.87: MCU1.16@1771.65,1094.49 R6.2@1783.46,1094.49
ESP_GPIO8: MCU1.7 R7.2 | length 458.4
  Top Layer w7.87: 1082.68,846.46 v1(1106.3,822.83) ; R7.2@1460.63,696.85 v1(1460.63,716.54)
  Bottom Layer w7.87: v1(1106.3,822.83) 1106.3,811.02 1200.79,716.54 v1(1460.63,716.54)
FUSED_IN: D5.2 F1.2 | length 7.9
  Top Layer w19.68: F1.2@248.03,594.49 D5.2@255.91,594.49
GND_BUS: C4.2 C20.2 C21.2 C22.2 C23.2 C25.2 C26.2 D1.2 D3.3 J1.3 U1.5 U2.2 U3.4 | length 1882.6
  Top Layer w15.75: v1(272.64,78.74) C22.2 ; U3.4 v1(500,478.35) ; v1(625.98,413.39) C20.2
  Top Layer w19.68: D3.3@188.98,795.28 v1(224.41,795.28) ; C22.2 C23.2 ; D1.2@374.02,685.04 v1(421.26,637.8) ; 389.76,149.61 437.01,196.85 586.61,196.85 U2.2@641.73,251.97 ; C25.2@456.69,318.9 v1(480.31,318.9) ; U1.5@586.61,952.76 610.24,929.13 C4.2@610.24,751.97 ; C4.2@633.86,720.47 633.86,598.43 645.67,586.61 ; C20.2@645.67,468.5 C21.2@645.67,476.38 ; U2.2@665.35,295.28 C26.2@665.35,318.9 ; C26.2@665.35,350.39 C20.2@665.35,358.27
  Bottom Layer w19.68: J1.3@118.11,669.29 118.11,677.17 224.41,783.46 ; v1(224.41,795.28) 251.97,795.28 v1@409.45,637.8 ; v1(421.26,637.8) 421.26,562.99 v1@496.06,488.19 ; v1(480.31,318.9) 555.12,393.7 555.12,421.26 ; v1(500,478.35) 555.12,431.1 608.27,431.1 v1(625.98,413.39)
GND_LOGIC: C5.2 C10.2 C11.2 C12.2 C27.2 C28.2 C29.2 C30.2 C32.2 C33.2 D6.2 J2.A1_B12 J2.B1_A12 J2.S1 J2.S2 J2.S3 J2.S4 MCU1.9 MCU1.19 R9.2 R10.2 R20.2 R21.2 SW1.2 SW2.2 U1.4 U2.4 U4.4 | length 3551.4
  Top Layer w7.87: v1(960.63,1129.92) C12.2 ; D6.2 1655.71,383.86 v1(1736.22,383.86)
  Top Layer w15.75: C32.2 C33.2 v1(1000,305.12) ; U4.4 v1(1230.32,614.17) ; C29.2 v1(1381.89,476.38)
  Top Layer w19.68: v1(889.76,1133.86) 889.76,1153.54 ; U2.4@897.64,275.59 956.69,334.65 ; U1.4@960.63,972.44 v1(960.63,1003.94) ; v1@964.57,1011.81 C10.2@980.32,1027.56 ; v1(1000,755.91) 1023.62,755.91 ; C32.2@1003.94,433.07 1015.75,433.07 ; C5.2@1011.81,728.35 1023.62,728.35 ; v1(1019.68,519.68) 1019.68,507.87 1066.93,460.63 C28.2@1094.49,460.63 ; 1082.68,759.84 v1(1102.36,759.84) ; v1(1291.34,960.63) MCU1.19@1381.89,960.63 ; C29.2@1322.83,511.81 1322.83,523.62 ; R20.2@1338.58,145.67 1338.58,125.98 1354.33,110.24 R9.2@1362.2,110.24 ; R20.2@1342.52,192.91 1358.27,192.91 R10.2@1362.2,196.85 ; R10.2@1385.83,228.35 1385.83,240.16 ; v1@1389.76,476.38 1444.88,421.26 1444.88,342.52 1433.07,330.71 R21.2@1433.07,311.02 ; 1433.07,240.16 J2.S1@1468.5,240.16 ; 1452.76,421.26 1543.31,511.81 ; J2.S1@1503.94,251.97 J2.A1_B12@1519.68,251.97 ; J2.B1_A12@1791.34,287.4 J2.S2@1807.09,287.4 ; 1814.96,291.34 1814.96,511.81
  Bottom Layer w19.68: v1(889.76,1133.86) v1@952.76,1133.86 ; v1@952.76,1011.81 925.2,1039.37 925.2,1062.99 960.63,1098.43 960.63,1118.11 ; v1(960.63,1003.94) 960.63,1007.87 980.32,1027.56 1003.94,1027.56 1074.8,956.69 1074.8,787.4 v1(1102.36,759.84) ; v1(1000,755.91) 1153.54,602.36 ; v1(1019.68,519.68) 1082.68,519.68 1173.23,610.24 v1@1220.47,610.24 ; 1082.68,960.63 v1(1291.34,960.63) ; v1(1230.32,614.17) 1368.11,476.38 v1(1381.89,476.38) ; J2.S3@1468.5,118.11 1460.63,118.11 1425.2,153.54 1425.2,177.17 1456.69,208.66 J2.S1@1468.5,208.66 ; J2.S1@1503.94,287.4 1594.49,377.95 v1@1728.35,377.95 ; 1724.41,370.08 J2.S2@1807.09,287.4 ; J2.S4@1807.09,118.11 J2.S2@1807.09,208.66
GPIO6: MCU1.5 R3.1 | length 606.4
  Top Layer w7.87: v1(992.13,996.06) 1023.62,996.06 ; R3.1@1204.72,661.42 1208.66,657.48 v1(1208.66,641.73)
  Bottom Layer w7.87: v1(992.13,996.06) 901.57,905.51 901.57,889.76 1129.92,661.42 1188.98,661.42 v1(1208.66,641.73)
GPIO7: MCU1.6 R4.2 | length 346.3
  Top Layer w7.87: 1082.68,905.51 1275.59,712.6 1326.77,712.6 R4.2@1342.52,696.85
NET_S: F1.1 J1.2 | length 43.3
  Top Layer w19.68: J1.2@141.73,500 F1.1@185.04,500
RXD: R4.1 U1.3 | length 630.9
  Top Layer w7.87: v1(929.13,897.64) 944.88,897.64 U1.3@948.82,901.57 ; R4.1@1311.02,661.42 1318.9,661.42 1338.58,641.73 1362.2,641.73 v1(1366.14,637.8)
  Bottom Layer w7.87: v1(929.13,897.64) 1129.92,696.85 1307.09,696.85 v1(1366.14,637.8)
SHIELD: J1.1 TP1.1 | length 55.1
  Top Layer w7.87: 98.43,295.28 J1.1@98.43,350.39
SW_BUS: C24.2 L2.1 U3.5 | length 200.6
  Top Layer w15.75: U3.5 C24.2
  Top Layer w19.68: L2.1@354.33,372.05 393.7,411.42 452.76,411.42 U3.5
SW_LOGIC: C31.2 L3.1 U4.5 | length 196.9
  Top Layer w15.75: U4.5 C31.2
  Top Layer w19.68: L3.1 1102.36,551.18 1161.42,551.18 U4.5
TXD: R2.2 R3.2 U1.2 | length 642.8
  Top Layer w7.87: U1.2@948.82,850.39 948.82,846.46 850.39,748.03 913.39,685.04 1141.73,685.04 1169.29,712.6 1220.47,712.6 R3.2@1236.22,696.85 ; R3.2@1259.84,661.42 1275.59,645.67 1295.28,645.67 R2.2@1314.96,625.98
USB_CC1: J2.A5 R9.1 | length 309.6
  Top Layer w5.91: R9.1@1393.7,47.24 1452.76,106.3 1452.76,125.98 1527.56,200.79 1562.99,200.79 1606.3,244.09 J2.A5@1606.3,248.03
USB_CC2: J2.B5 R10.1 | length 367.3
  Top Layer w5.91: R10.1@1393.7,165.35 v1(1456.69,165.35) ; v1(1527.56,165.35) 1645.67,165.35 1724.41,244.09 J2.B5@1724.41,248.03
  Bottom Layer w5.91: v1(1456.69,165.35) v1(1527.56,165.35)
USB_DM: D6.6 R11.1 | length 602.6
  Top Layer w5.91: D6.6 1618.31,478.35 1740.16,478.35 1775.59,513.78 1775.59,661.42 1854.33,740.16 1854.33,846.46 R11.1
USB_DM_IN: D6.1 J2.A7 J2.B7 | length 156
  Top Layer w5.91: D6.1 1618.31,312.99 1626.18,305.12 ; J2.B7 1626.18,305.12 ; J2.A7 1665.55,305.12 1626.18,305.12
USB_DM_MCU: MCU1.13 R11.2 | length 96.7
  Top Layer w5.91: MCU1.13 R11.2
USB_DP: D6.4 R12.1 | length 719.6
  Top Layer w5.91: D6.4 1718.7,464.57 1753.94,464.57 1793.31,503.94 1793.31,661.42 1872.05,740.16 1872.05,1015.75 R12.1
USB_DP_IN: D6.3 J2.A6 J2.B6 | length 184.8
  Top Layer w5.91: J2.A6 1645.87,238.19 1685.24,238.19 J2.B6 1685.24,301.18 1693.11,309.06 D6.3
USB_DP_MCU: MCU1.14 R12.2 | length 96.9
  Top Layer w5.91: MCU1.14 R12.2
USB_VBUS: D4.2 D6.5 J2.A4_B9 J2.B4_A9 | length 429.3
  Top Layer w7.87: J2.A4_B9@1555.12,291.34 D4.2@1555.12,350.39 ; 1657.48,401.57 1712.6,401.57 1720.47,409.45 1748.03,409.45 1763.78,393.7 1763.78,374.02 1755.91,366.14 J2.B4_A9@1755.91,291.34
  Top Layer w11.81: D4.2 1584.65,403.15 1655.71,403.15 D6.5
pads on no net: J2. J2.A8 J2.B8 MCU1.3 MCU1.4 MCU1.10 MCU1.11 MCU1.12 MCU1.15 MCU1.17 MCU1.18

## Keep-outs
Keep-Out Layer:
  region: 710.63,5.91 824.8,5.91 824.8,1253.94 710.63,1253.94
  region: 5.91,190.94 17.72,190.94 17.72,399.61 5.91,399.61
  region: 210.63,5.91 419.29,5.91 419.29,17.72 210.63,17.72
  region: 289.37,1242.13 498.03,1242.13 498.03,1253.94 289.37,1253.94
  region: 1872.05,309.06 1883.86,309.06 1883.86,517.72 1872.05,517.72

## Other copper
Top Layer:
  drawing of 35 lines, arcs and shapes, not listed
Bottom Layer:
  drawing of 61 lines, arcs and shapes, not listed

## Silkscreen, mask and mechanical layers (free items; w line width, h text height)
Top Overlay:
  lines w5.91: 236.22,1141.73 236.22,1181.1 255.91,1181.1 255.91,1161.42 236.22,1161.42 ; 246.06,1161.42 255.91,1141.73 ; 265.75,1181.1 265.75,1161.42 285.43,1161.42 ; 285.43,1141.73 285.43,1181.1 ; 344.49,1141.73 344.49,1181.1 324.8,1181.1 324.8,1161.42 344.49,1161.42 ; 354.33,1161.42 374.02,1161.42 ; 383.86,1141.73 403.54,1141.73 ; 383.86,1171.26 393.7,1181.1 393.7,1141.73 ; 413.39,1161.42 433.07,1161.42 433.07,1141.73 413.39,1141.73 413.39,1181.1 433.07,1181.1 ; 442.91,1181.1 452.76,1141.73 462.6,1181.1
Bottom Overlay:
  lines w5.91: 181.1,413.39 200.79,413.39 200.79,393.7 181.1,393.7 181.1,374.02 200.79,374.02 ; 188.98,511.81 208.66,511.81 ; 188.98,629.92 208.66,629.92 ; 188.98,728.35 188.98,767.72 ; 188.98,748.03 208.66,748.03 ; 188.98,846.46 208.66,846.46 208.66,885.83 ; 198.82,492.13 198.82,531.5 ; 208.66,728.35 208.66,767.72 ; 240.16,374.02 259.84,374.02 ; 250,374.02 250,413.39 259.84,403.54 ; 521.65,1171.26 541.34,1171.26 ; 521.65,1181.1 531.5,1161.42 541.34,1181.1 ; 551.18,1141.73 570.87,1141.73 570.87,1181.1 551.18,1181.1 ; 561.02,1161.42 570.87,1161.42 ; 580.71,1141.73 580.71,1181.1 590.55,1161.42 600.39,1181.1 600.39,1141.73 ; 610.24,1181.1 610.24,1141.73 629.92,1181.1 629.92,1141.73 ; 1417.32,661.42 1437.01,661.42 ; 1427.17,622.05 1427.17,661.42 ; 1446.85,622.05 1466.54,622.05 1466.54,661.42 1446.85,661.42 ; 1456.69,641.73 1466.54,641.73 ; 1476.38,661.42 1496.06,661.42 1496.06,641.73 1476.38,641.73 1476.38,622.05 1496.06,622.05 ; 1505.91,622.05 1525.59,622.05 1525.59,661.42 1505.91,661.42 ; 1515.75,641.73 1525.59,641.73 ; 1535.43,622.05 1545.28,641.73 ; 1555.12,622.05 1555.12,661.42 1535.43,661.42 1535.43,641.73 1555.12,641.73 ; 1641.73,98.43 1631.89,98.43 ; 1651.57,118.11 1671.26,118.11 1671.26,98.43 1651.57,98.43 1651.57,78.74 1671.26,78.74 ; 1681.1,118.11 1681.1,78.74 1700.79,78.74 1700.79,118.11 ; 1702.76,661.42 1722.44,661.42 ; 1712.6,622.05 1712.6,661.42 ; 1811.02,641.73 1801.18,641.73 ; 1631.89,98.43 1622.05,108.27 1631.89,118.11 1641.73,118.11 1641.73,78.74 1631.89,78.74 1622.05,88.58 1631.89,98.43 ; 1801.18,641.73 1791.34,651.57 1801.18,661.42 1811.02,661.42 1811.02,622.05 1801.18,622.05 1791.34,631.89 1801.18,641.73 ; 1732.28,622.05 1732.28,661.42 1751.97,661.42 1751.97,622.05 1732.28,622.05 ; 1761.81,622.05 1761.81,661.42 1781.5,661.42 1781.5,622.05 1761.81,622.05
Board outline:
  drawing of 260 lines, arcs and shapes, not listed
Isolation and RF planning:
  lines w3.94: 0,185.04 23.62,185.04 23.62,405.51 0,405.51 0,185.04 ; 204.72,0 425.2,0 425.2,23.62 204.72,23.62 204.72,0 ; 283.46,1236.22 503.94,1236.22 503.94,1259.84 283.46,1259.84 283.46,1236.22 ; 704.72,0 830.71,0 830.71,1259.84 704.72,1259.84 704.72,0 ; 1866.14,303.15 1889.76,303.15 1889.76,523.62 1866.14,523.62 1866.14,303.15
